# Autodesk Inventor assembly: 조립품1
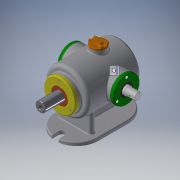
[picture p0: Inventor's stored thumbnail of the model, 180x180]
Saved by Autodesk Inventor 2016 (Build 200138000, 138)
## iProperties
Created: 2018-02
Part Number: 조립품1
Material: 일반
Document SubType Name: Assembly
Designer: 605-11
Author: 605-11
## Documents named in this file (16)
- C:\Users\605-11\Desktop\380207V1003\답안조립품.iam
- C:\Users\605-11\Desktop\380207V1003\본체.ipt
- C:\Users\605-11\Desktop\380207V1003\본체커버.ipt
- C:\Users\605-11\Desktop\380207V1003\베어링 6205.ipt
- 베어링 6205.ipt
- C:\Users\605-11\Desktop\380207V1003\축 커버-1.ipt
- C:\Users\605-11\Desktop\380207V1003\축 커버-2.ipt
- C:\Users\605-11\Desktop\380207V1003\오일실.ipt
- 오일실.ipt
- C:\Users\605-11\Desktop\380207V1003\슬라이드 커버.ipt
- C:\Users\605-11\Desktop\380207V1003\부시.ipt
- C:\Users\605-11\Desktop\380207V1003\슬라이드.ipt
- C:\Users\605-11\Desktop\380207V1003\편심축.ipt
- C:\Users\605-11\Desktop\380207V1003\상부 캡.ipt
- C:\Users\605-11\Desktop\380207V1003\볼트 M4.ipt
- C:\Users\605-11\Desktop\380207V1003\가변스프링.ipt
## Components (1 placed, 1 different names)
1. 가변스프링:1
